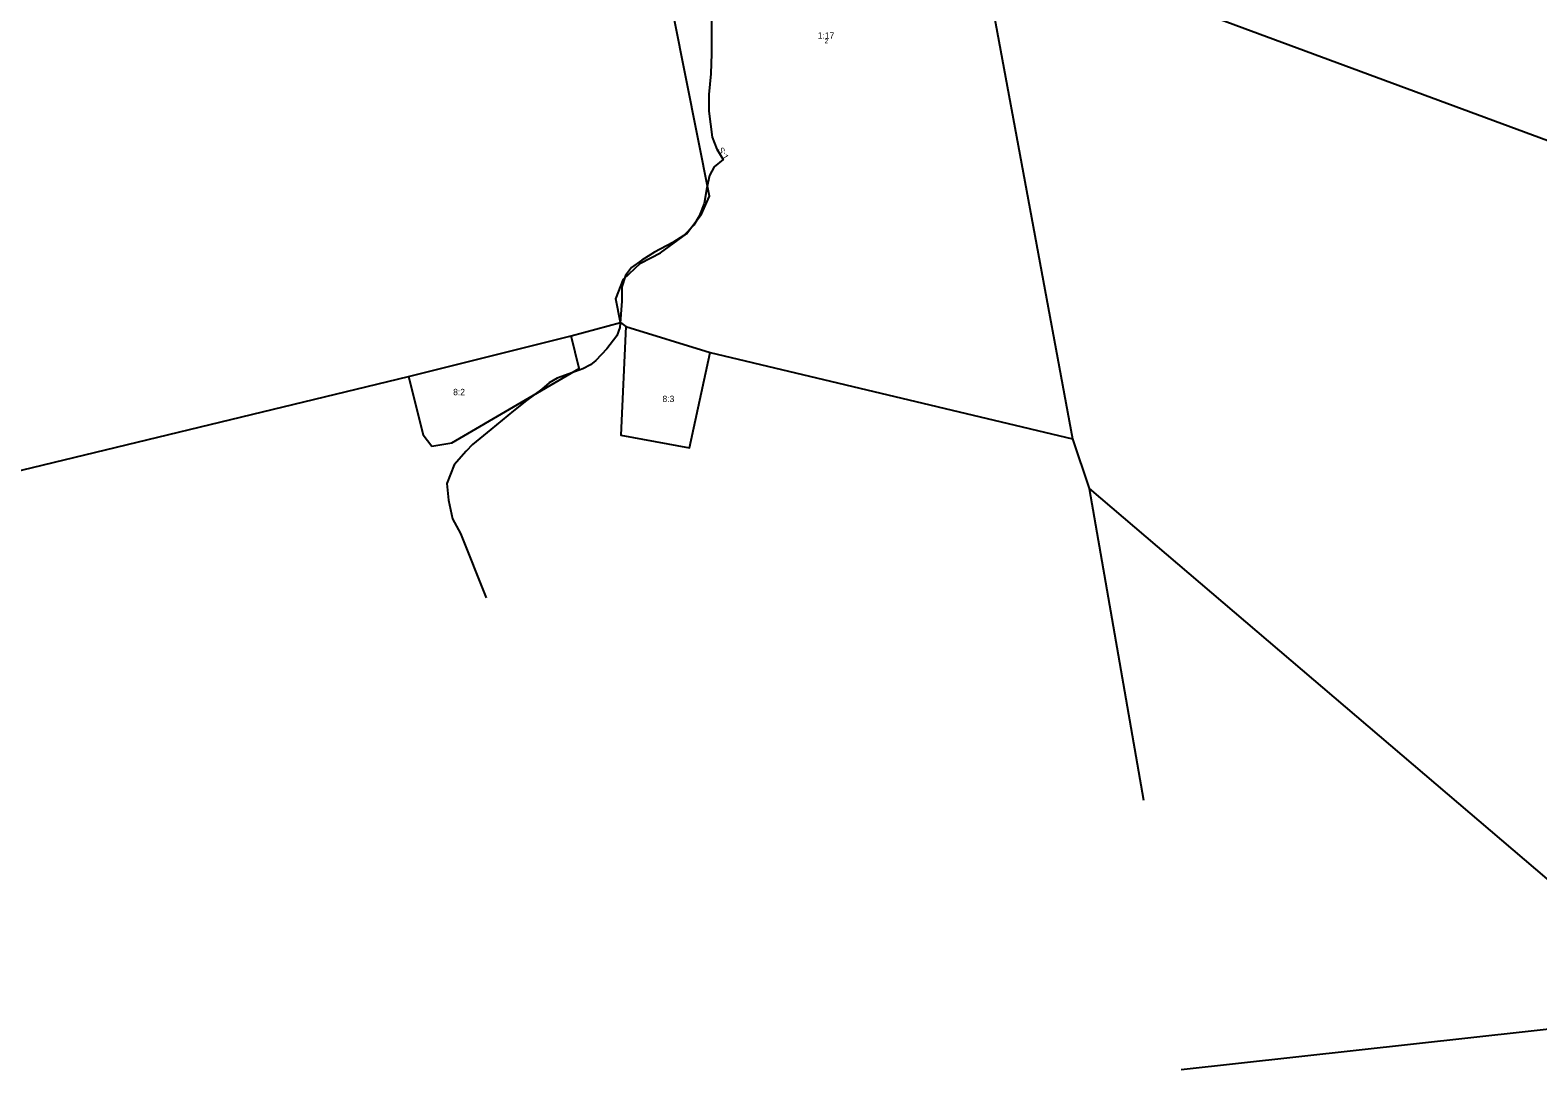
# Model space of a CAD drawing. Extents: x 140824 to 143748, y 6547319 to 6550906.
# Drawn here: x 141835 to 142666, y 6547319 to 6547892 of the extents above; entities that cross this region are included whole.
import ezdxf

# ---------------------------------------------------------------- set-up
doc = ezdxf.new("R2010")
doc.units = 0
for name, color, linetype in [('FAST Fastighetsgräns', 7, 'Continuous'), ('FAST Mittlinjeredovisad samfällighet', 7, 'Continuous'), ('FAST Områdesnummer för fastighet', 7, 'Continuous'), ('FAST Registernummer för fastighet', 7, 'Continuous'), ('FAST Registernummer för mittlinjeredovisad samfällighet', 7, 'Continuous'), ('FAST Traktgräns', 7, 'Continuous')]:
    doc.layers.add(name, color=color, linetype=linetype)

msp = doc.modelspace()

# ---------------------------------------------------------------- linework, layer by layer
at = {"layer": 'FAST Fastighetsgräns'}
for p, q in [((142163.17, 6547728.84), (142209.76, 6547714.52)), ((142043.35, 6547701.25), (142133.01, 6547723.7))]:
    msp.add_line(p, q, dxfattribs=at)
msp.add_lwpolyline([(142160.23, 6547730.93), (142157.6, 6547744), (142161.92, 6547754.88), (142171.18, 6547763.62), (142182.34, 6547769.3), (142196.65, 6547779.9), (142204.97, 6547790.66), (142209.25, 6547800.54), (142156.88, 6548064.06)], dxfattribs=at)
at = {"layer": 'FAST Mittlinjeredovisad samfällighet'}
msp.add_lwpolyline([(142210.33, 6547910.44), (142210.35, 6547890.57), (142210.48, 6547879.27), (142209.99, 6547868), (142209.02, 6547856.69), (142208.85, 6547847.37), (142210.72, 6547833.19), (142213.43, 6547826.55), (142216.81, 6547820.86), (142211.85, 6547816.79), (142209.37, 6547811.96), (142207.89, 6547805.18), (142206.39, 6547796.58), (142203.62, 6547789.57), (142200.58, 6547784.58), (142195.15, 6547779), (142189.08, 6547775.01), (142179.04, 6547769.65), (142171.99, 6547765.42), (142166.38, 6547761.21), (142162.94, 6547756.88), (142160.88, 6547750.61), (142160.93, 6547742.77), (142159.86, 6547728.28), (142158.23, 6547723.55), (142152.73, 6547716.49), (142146.57, 6547710.02), (142143.71, 6547707.55), (142139.55, 6547705.36), (142125.33, 6547700.27), (142120.98, 6547697.75), (142116.9, 6547694.3), (142108.46, 6547688), (142101.22, 6547682.27), (142088.78, 6547672.04), (142078.62, 6547663.64), (142075.17, 6547659.99), (142068.57, 6547652.44), (142064.53, 6547642.15), (142065.47, 6547633.11), (142067.66, 6547622.82), (142072.03, 6547614.72), (142086.09, 6547579.19)], dxfattribs=at)
at = {"layer": 'FAST Traktgräns'}
for p, q in [((142357.53, 6547947.34), (142409.38, 6547666.8)), ((142922.53, 6547738.17), (142357.53, 6547947.34)), ((142133.01, 6547723.7), (142160.23, 6547730.93)), ((142160.23, 6547730.93), (142163.17, 6547728.84)), ((142209.76, 6547714.52), (142409.38, 6547666.8)), ((142043.35, 6547701.25), (142051.41, 6547669.02)), ((142051.41, 6547669.02), (142056.24, 6547662.88)), ((142409.38, 6547666.8), (142418.59, 6547639.53)), ((142418.59, 6547639.53), (142448.62, 6547467.66))]:
    msp.add_line(p, q, dxfattribs=at)
for points in [[(142163.17, 6547728.84), (142160.43, 6547668.92), (142198.23, 6547661.84), (142209.76, 6547714.52)], [(142056.24, 6547662.88), (142067.29, 6547664.57), (142137.49, 6547705.57), (142133.01, 6547723.7)], [(141669.8, 6547649.89), (141795.57, 6547641.3), (142043.35, 6547701.25)], [(142418.59, 6547639.53), (142757.29, 6547350.84), (142469.32, 6547319.05)]]:
    msp.add_lwpolyline(points, dxfattribs=at)

# ---------------------------------------------------------------- texts
at = {"layer": 'FAST Områdesnummer för fastighet'}
msp.add_text('2', height=2.5, dxfattribs=at).set_placement((142272.75, 6547884.87))
at = {"layer": 'FAST Registernummer för fastighet'}
for s, p in [('1:17', (142268.98, 6547887.37)), ('8:2', (142067.97, 6547690.9)), ('8:3', (142183.39, 6547687.11))]:
    msp.add_text(s, height=3.5, dxfattribs=at).set_placement(p)
at = {"layer": 'FAST Registernummer för mittlinjeredovisad samfällighet'}
msp.add_text('S:1', height=3.5, rotation=300.595, dxfattribs=at).set_placement((142213.61, 6547826.27))

doc.saveas('drawing.dxf')
